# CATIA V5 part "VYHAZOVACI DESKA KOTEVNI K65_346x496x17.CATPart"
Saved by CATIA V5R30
Part number: VYHAZOVACI DESKA KOTEVNI
Bounding box of the stored display mesh (mm): x 0 to 17, y -150 to 150, z -173 to 173
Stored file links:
  C:\Users\ondra\Desktop\PŘÍLOHA P III\CATIA\VYHAZOVACI DESKA KOTEVNI K65_346x496x17.CATPart
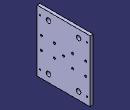
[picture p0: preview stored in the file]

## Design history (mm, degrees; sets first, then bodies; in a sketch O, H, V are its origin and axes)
Set1
  DatumSurface1 to DatumSurface14 "K65/346x"
  Plane1: type Offset, RefPlane yz-plane, Offset 17
  Join1: Elements (DatumSurface1; DatumSurface2; DatumSurface3; DatumSurface4; DatumSurface5; DatumSurface6; DatumSurface7; DatumSurface8; DatumSurface9; DatumSurface10; DatumSurface11; DatumSurface12; DatumSurface13; DatumSurface14)
Body1 (main body)
  DatumPoint1
  CloseSurface1: CloseElement Join1
  Sketch1 on {plane type Tangent, Support face of CloseSurface1, RefPoint vertex of DatumPoint1}, origin (39, -85, -130), H (0, 1, 0), V (0, 0, -1)
    point P1 (0, 0)
    reference projected point E1 (0, 0) from vertex of DatumPoint1
    coincidence: E1 P1
  Hole1: placed by Sketch1, at (17, -85, -130) direction (-1, 0, 0), diameter 26, through (limit type 6)
  Sketch2, origin (39, 0, 0), H (0, 1, 0), V (0, 0, -1), geometry linked from another document
  UserPattern1: of Hole1, copies 4, at the points of Sketch2
  Plane2: type Offset, RefPlane yz-plane, Offset 17
  DatumSurface15
  DatumSurface16
  Sketch3 on Plane2, origin (17, 0, 0), H (0, 1, 0), V (0, 0, 1)
    reference projected circle E1 centre (-88.524, 0) radius 55.0098 from face of DatumSurface15
    reference projected circle E2 centre (-88.524, 0) radius 48.8976 from face of DatumSurface15
    construction line L1 (0, 0) -> (-169.4678, 0)
    construction circle A1 centre (-140.4777, 0) radius 3.0561
    point P2 (-140.4777, 0)
    construction line L2 (-88.524, 0) -> (-88.524, -6.5413)
    point P3 (-88.524, 0)
    construction circle A2 centre (-88.524, -51.9537) radius 3.0561
    point P5 (-88.524, -51.9537)
    point P6 (-36.5703, 0)
    construction circle A3 centre (-36.5703, 0) radius 3.0561
    point P7 (-88.524, 51.9537)
    construction circle A4 centre (-88.524, 51.9537) radius 3.0561
    point P8 (-36.5703, 0)
    point P9 (-88.524, -51.9537)
    point P10 (-88.524, 51.9537)
    point P11 (-140.4777, 0)
    point P12 (140.4777, 0)
    point P13 (88.524, -51.9537)
    point P14 (36.5703, 0)
    point P15 (88.524, 51.9537)
    construction line L3 (-88.524, 0) -> (-49.6262, 38.8978)
    point P16 (-49.6262, 38.8978)
    construction circle A5 centre (-51.7872, 36.7368) radius 3.0561
    point P17 (-51.7872, 36.7368)
    point P18 (-53.9482, 34.5758)
    point P19 (-51.7872, 36.7368)
    point P20 (-51.7872, -36.7368)
    point P21 (-125.2609, 36.7368)
    point P22 (-125.2609, -36.7368)
    point P23 (125.2609, 36.7368)
    point P24 (125.2609, -36.7368)
    point P25 (51.7872, -36.7368)
    point P26 (51.7872, 36.7368)
    angle L3 H = 45
    horizontal: L1 H
    coincidence: P2 L1, P5 L2, P8 P6, P9 P5, P10 P7, P11 P2, P16 E1, P17 L3, A5 P18, P18 E2, P19 P17
    tangency: A1 E2, A1 E1, A2 E2, A2 E1, A5 E1, A5 E2
    concentricity: P3 E2
    vertical: L2 V
    symmetry: A1 A3 L2, A2 A4 L1, P11 P12 V, P9 P13 V, P8 P14 V, P10 P15 V, P19 P20 H, P19 P21 L2, P20 P22 L2, P21 P23 V, P22 P24 V, P20 P25 V, P19 P26 V
  Plane3: type Offset, RefPlane yz-plane, Offset 17
  Sketch4 on {plane type Tangent, Support face of CloseSurface1, RefPoint Sketch3.P21}, origin (17, -125.2609, 36.7368), H (0, 1, 0), V (0, 0, -1)
    point P1 (0, 0)
    reference projected point E1 (0, 0) from Sketch3.P21
    coincidence: E1 P1
  Hole2: placed by Sketch4, at (17, -125.2609, 36.7368) direction (-1, 0, 0), diameter 6.5, through (limit type 6), counterbore diameter 12, counterbore depth 5
  UserPattern2: of Hole2, copies 8, at the points of Sketch3
  Sketch5 on yz-plane, origin (0, 0, 0), H (0, 1, 0), V (0, 0, 1)
    point P1 (0, 0)
    coincidence: P1 O
  Sketch6 on {plane type Tangent, Support face of CloseSurface1, RefPoint Sketch5.P1}, origin (0, 0, 0), H (0, 1, 0), V (0, 0, -1)
    point P1 (0, 0)
    reference projected point E1 (0, 0) from Sketch5.P1
    coincidence: E1 P1
  Hole3: placed by Sketch6, at (17, 0, 0) direction (-1, 0, 0), diameter 6.5, through (limit type 6), counterbore diameter 12, counterbore depth 5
